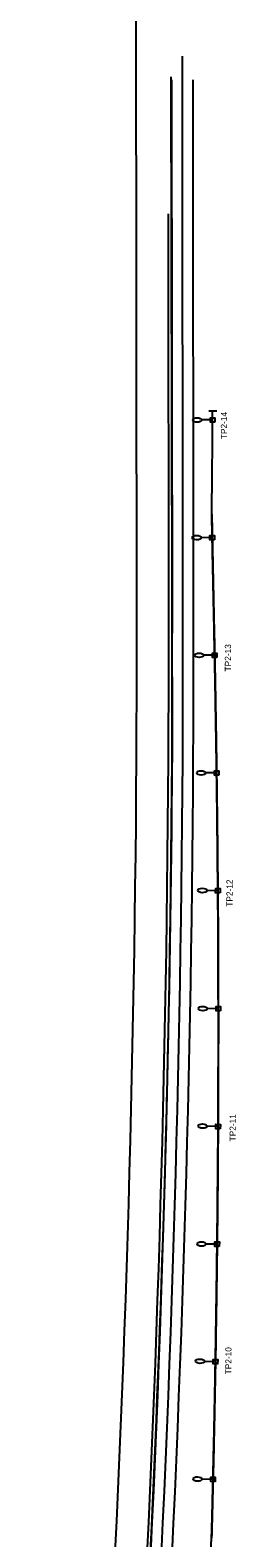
# Model space of a CAD drawing. Extents: x 172067 to 172728, y 250510 to 260293.
# Drawn here: x 172392 to 172623, y 257350 to 259050 of the extents above; entities that cross this region are included whole.
import ezdxf

# ---------------------------------------------------------------- set-up
doc = ezdxf.new("R2010")
doc.units = 0
for name, color, linetype in [('_CIVIL_CONSTRUCTION', 7, 'Continuous'), ('CM_Corridor_Final', 7, 'Continuous'), ('DR_P_Ditch', 7, 'Continuous'), ('DT_P_Graded_Shoulder', 7, 'Continuous'), ('MD_P_ACSC_T', 7, 'Continuous'), ('MD_P_Surface_Aggregate_Base', 7, 'Continuous'), ('MD_P_Surface_Ditch', 7, 'Continuous'), ('MD_P_Surface_Finished_Grade', 7, 'Continuous'), ('SC_Scratch1', 7, 'Continuous')]:
    doc.layers.add(name, color=color, linetype=linetype)

msp = doc.modelspace()

# ---------------------------------------------------------------- linework, layer by layer
at = {"layer": '_CIVIL_CONSTRUCTION'}
msp.add_line((172551.8, 258224.3), (172550.5, 258997.5), dxfattribs=at)
msp.add_arc((151025.4, 258373.7), 21526.9, 355.24419, 359.60258, dxfattribs=at)
at = {"layer": 'CM_Corridor_Final'}
for p, q in [((172597.2, 258610.5), (172584.7, 258610.5)), ((172596.7, 258477.7), (172584.2, 258477.8)), ((172599.5, 258345.1), (172587, 258345.1)), ((172601.7, 258212.3), (172589.2, 258212.4)), ((172603, 258079.5), (172590.5, 258079.7)), ((172603.6, 257946.4), (172591.1, 257946.5)), ((172603.3, 257813.5), (172590.8, 257813.8)), ((172602.2, 257680.8), (172589.7, 257680.9)), ((172600.3, 257548.1), (172587.8, 257548.6)), ((172597.6, 257415.5), (172585.1, 257415.8))]:
    msp.add_line(p, q, dxfattribs=at)
for points in [[(172599.7, 258608), (172594.7, 258608), (172594.7, 258613), (172599.7, 258613)], [(172599.2, 258475.2), (172594.2, 258475.2), (172594.2, 258480.2), (172599.2, 258480.2)], [(172602, 258342.6), (172597, 258342.6), (172597, 258347.6), (172602, 258347.6)], [(172604.1, 258209.8), (172599.1, 258209.8), (172599.2, 258214.8), (172604.2, 258214.8)], [(172605.5, 258077), (172600.5, 258077.1), (172600.6, 258082.1), (172605.6, 258082)], [(172606.1, 257943.9), (172601.1, 257943.9), (172601.1, 257948.9), (172606.1, 257948.9)], [(172605.8, 257811), (172600.8, 257811.1), (172600.9, 257816.1), (172605.9, 257816)], [(172604.7, 257678.3), (172599.7, 257678.3), (172599.8, 257683.3), (172604.8, 257683.3)], [(172602.7, 257545.6), (172597.7, 257545.7), (172597.9, 257550.7), (172602.9, 257550.6)], [(172600.1, 257412.9), (172595.1, 257413), (172595.2, 257418), (172600.2, 257417.9)]]:
    msp.add_lwpolyline(points, close=True, dxfattribs=at)
for centre, major_axis in [((172579.7, 258610.5), (-5, 0)), ((172579.2, 258477.8), (-5, 0.03)), ((172582, 258345.1), (-5, 0)), ((172584.2, 258212.4), (-5, 0.03)), ((172585.5, 258079.8), (-5, 0.06)), ((172586.1, 257946.6), (-5, 0.06)), ((172585.8, 257814), (-5, 0.12)), ((172584.7, 257681), (-5, 0.06)), ((172582.9, 257548.8), (-5, 0.19)), ((172580.1, 257415.9), (-5, 0.12))]:
    msp.add_ellipse(centre, major_axis=major_axis, ratio=0.5, dxfattribs=at)
at = {"layer": 'DR_P_Ditch'}
for points in [[(172599.5, 258345.1), (172599.2, 258355.6), (172598.8, 258377.6), (172598.2, 258406.5), (172597.7, 258429.6), (172597.2, 258453.1), (172596.9, 258468.4), (172596.6, 258484.3), (172596.2, 258503.9), (172596.9, 258574.2), (172597.2, 258602.5), (172597.2, 258610.5)], [(172603, 258079.5), (172602.8, 258104.5), (172602.5, 258137.4), (172602.2, 258171.4), (172601.9, 258192.3), (172601.8, 258202.5), (172601.5, 258220.1), (172601.3, 258238.9), (172600.9, 258263.8), (172600.4, 258291.3), (172600.1, 258311.4), (172599.7, 258333.1), (172599.6, 258339.5), (172599.5, 258345.1)], [(172603.3, 257813.5), (172603.4, 257830.1), (172603.5, 257855.7), (172603.6, 257882), (172603.6, 257910), (172603.6, 257936.2), (172603.6, 257956), (172603.5, 257974.8), (172603.5, 257996.8), (172603.4, 258014.7), (172603.3, 258039.6), (172603.2, 258060.8), (172603.1, 258071.9), (172603, 258079.5)], [(172600.3, 257548.1), (172600.7, 257570.4), (172601, 257591.2), (172601.3, 257610.3), (172601.7, 257639.7), (172602, 257663.1), (172602.4, 257697.5), (172602.6, 257721), (172603, 257761.5), (172603.2, 257787.2), (172603.3, 257802.2), (172603.3, 257813.5)], [(172592.8, 257282.5), (172593.2, 257291.3), (172594.5, 257318.9), (172595.7, 257344.1), (172596.3, 257360.2), (172596.8, 257380.5), (172597.4, 257406.3), (172597.8, 257422.5), (172598.1, 257437.6), (172598.5, 257453.7), (172598.7, 257463.4), (172599.1, 257481.4), (172599.5, 257502.1), (172599.9, 257524.1), (172600.1, 257534.9), (172600.3, 257548.1)]]:
    msp.add_open_spline(points, degree=2, dxfattribs=at)
at = {"layer": 'DT_P_Graded_Shoulder'}
for p, q in [((172601.9, 258620.6), (172592.9, 258620.6)), ((172597.2, 258610.5), (172597.2, 258620.6))]:
    msp.add_line(p, q, dxfattribs=at)
at = {"layer": 'MD_P_ACSC_T'}
msp.add_lwpolyline([(172596.2, 258504.2), (172599, 258370.4), (172599, 258370.4)], dxfattribs=at)
msp.add_open_spline([(172599, 258370.4), (172599.1, 258364.3), (172599.3, 258355.5), (172599.6, 258340.1), (172599.7, 258334.6), (172599.8, 258326), (172599.9, 258323.1), (172600, 258317.2), (172600, 258314.2), (172600.3, 258299.2), (172600.5, 258286.9), (172600.8, 258272.3), (172600.8, 258269.4), (172600.9, 258263.8), (172600.9, 258261), (172601.1, 258252.8), (172601.2, 258247.5), (172601.3, 258237), (172601.4, 258231.8), (172601.5, 258224), (172601.5, 258221.4), (172601.6, 258216.2), (172601.6, 258213.6), (172601.8, 258200.5), (172601.9, 258189.8), (172602.1, 258173.7), (172602.2, 258168.4), (172602.3, 258157.7), (172602.4, 258152.4), (172602.5, 258136.4), (172602.6, 258125.8), (172602.8, 258104.6), (172602.9, 258094), (172603.1, 258072.7), (172603.1, 258062), (172603.3, 258040.8), (172603.3, 258030.1), (172603.4, 258008.9), (172603.5, 257998.3), (172603.6, 257945.1), (172603.6, 257902.6), (172603.4, 257817.5), (172603.1, 257775), (172602.7, 257721.8), (172602.6, 257711.2), (172602.3, 257689.9), (172602.2, 257679.3), (172602, 257658), (172601.8, 257647.4), (172601.6, 257626.1), (172601.4, 257615.5), (172601.1, 257594.2), (172600.9, 257583.6), (172600.7, 257567.7), (172600.6, 257562.4), (172600.4, 257551.7), (172600.3, 257546.3), (172600, 257530.3), (172599.8, 257519.6), (172599.6, 257506.4), (172599.5, 257503.8), (172599.4, 257498.6), (172599.4, 257496), (172599.2, 257488.3), (172599.1, 257483.1), (172598.9, 257472.6), (172598.8, 257467.3), (172598.6, 257459.1), (172598.6, 257456.3), (172598.4, 257450.6), (172598.4, 257447.8), (172598, 257433.2), (172597.8, 257420.8), (172597.4, 257405.8), (172597.3, 257402.9), (172597.2, 257397), (172597.1, 257394.1), (172596.9, 257385.5), (172596.8, 257380), (172596.4, 257364.6), (172596.1, 257355.8), (172596, 257349.7)], degree=3, dxfattribs=at)
at = {"layer": 'MD_P_Surface_Aggregate_Base'}
msp.add_line((172547.8, 258370), (172547.4, 258842.9), dxfattribs=at)
msp.add_arc((151025.9, 258352.5), 21521.9, 353.94188, 0.0466, dxfattribs=at)
at = {"layer": 'MD_P_Surface_Ditch'}
msp.add_line((172563.8, 258370), (172563.2, 259020.8), dxfattribs=at)
msp.add_arc((151025.9, 258352.5), 21537.9, 353.94188, 0.0466, dxfattribs=at)
at = {"layer": 'MD_P_Surface_Finished_Grade'}
for p, q in [((172551.8, 258370), (172551.3, 258994.3)), ((172575.8, 258370), (172575.3, 258994.3))]:
    msp.add_line(p, q, dxfattribs=at)
for radius in [21525.9, 21549.9]:
    msp.add_arc((151025.9, 258352.5), radius, 353.94188, 0.0466, dxfattribs=at)
at = {"layer": 'SC_Scratch1'}
msp.add_line((172511.8, 258370), (172510.2, 260292.5), dxfattribs=at)
msp.add_line((172511.8, 258370), (172510.2, 260292.5), dxfattribs=at)
msp.add_line((172511.8, 258370), (172510.2, 260292.5), dxfattribs=at)
msp.add_line((172511.8, 258370), (172510.2, 260292.5), dxfattribs=at)
msp.add_arc((151025.9, 258352.5), 21485.9, 353.94188, 0.0466, dxfattribs=at)
msp.add_arc((151025.9, 258352.5), 21485.9, 353.94188, 0.0466, dxfattribs=at)
msp.add_arc((151025.9, 258352.5), 21485.9, 353.94188, 0.0466, dxfattribs=at)
msp.add_arc((151025.9, 258352.5), 21485.9, 353.94188, 0.0466, dxfattribs=at)

# ---------------------------------------------------------------- texts
at = {"layer": 'MD_P_ACSC_T'}
for s, p in [('TP2-14', (172613.4, 258588.9)), ('TP2-13', (172617.9, 258326.9)), ('TP2-12', (172619.7, 258061.5)), ('TP2-11', (172623.2, 257796.8)), ('TP2-10', (172618.4, 257534))]:
    msp.add_text(s, height=7, rotation=89.9803, dxfattribs=at).set_placement(p)

doc.saveas('drawing.dxf')
